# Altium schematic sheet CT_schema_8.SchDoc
size 382 x 278 mm
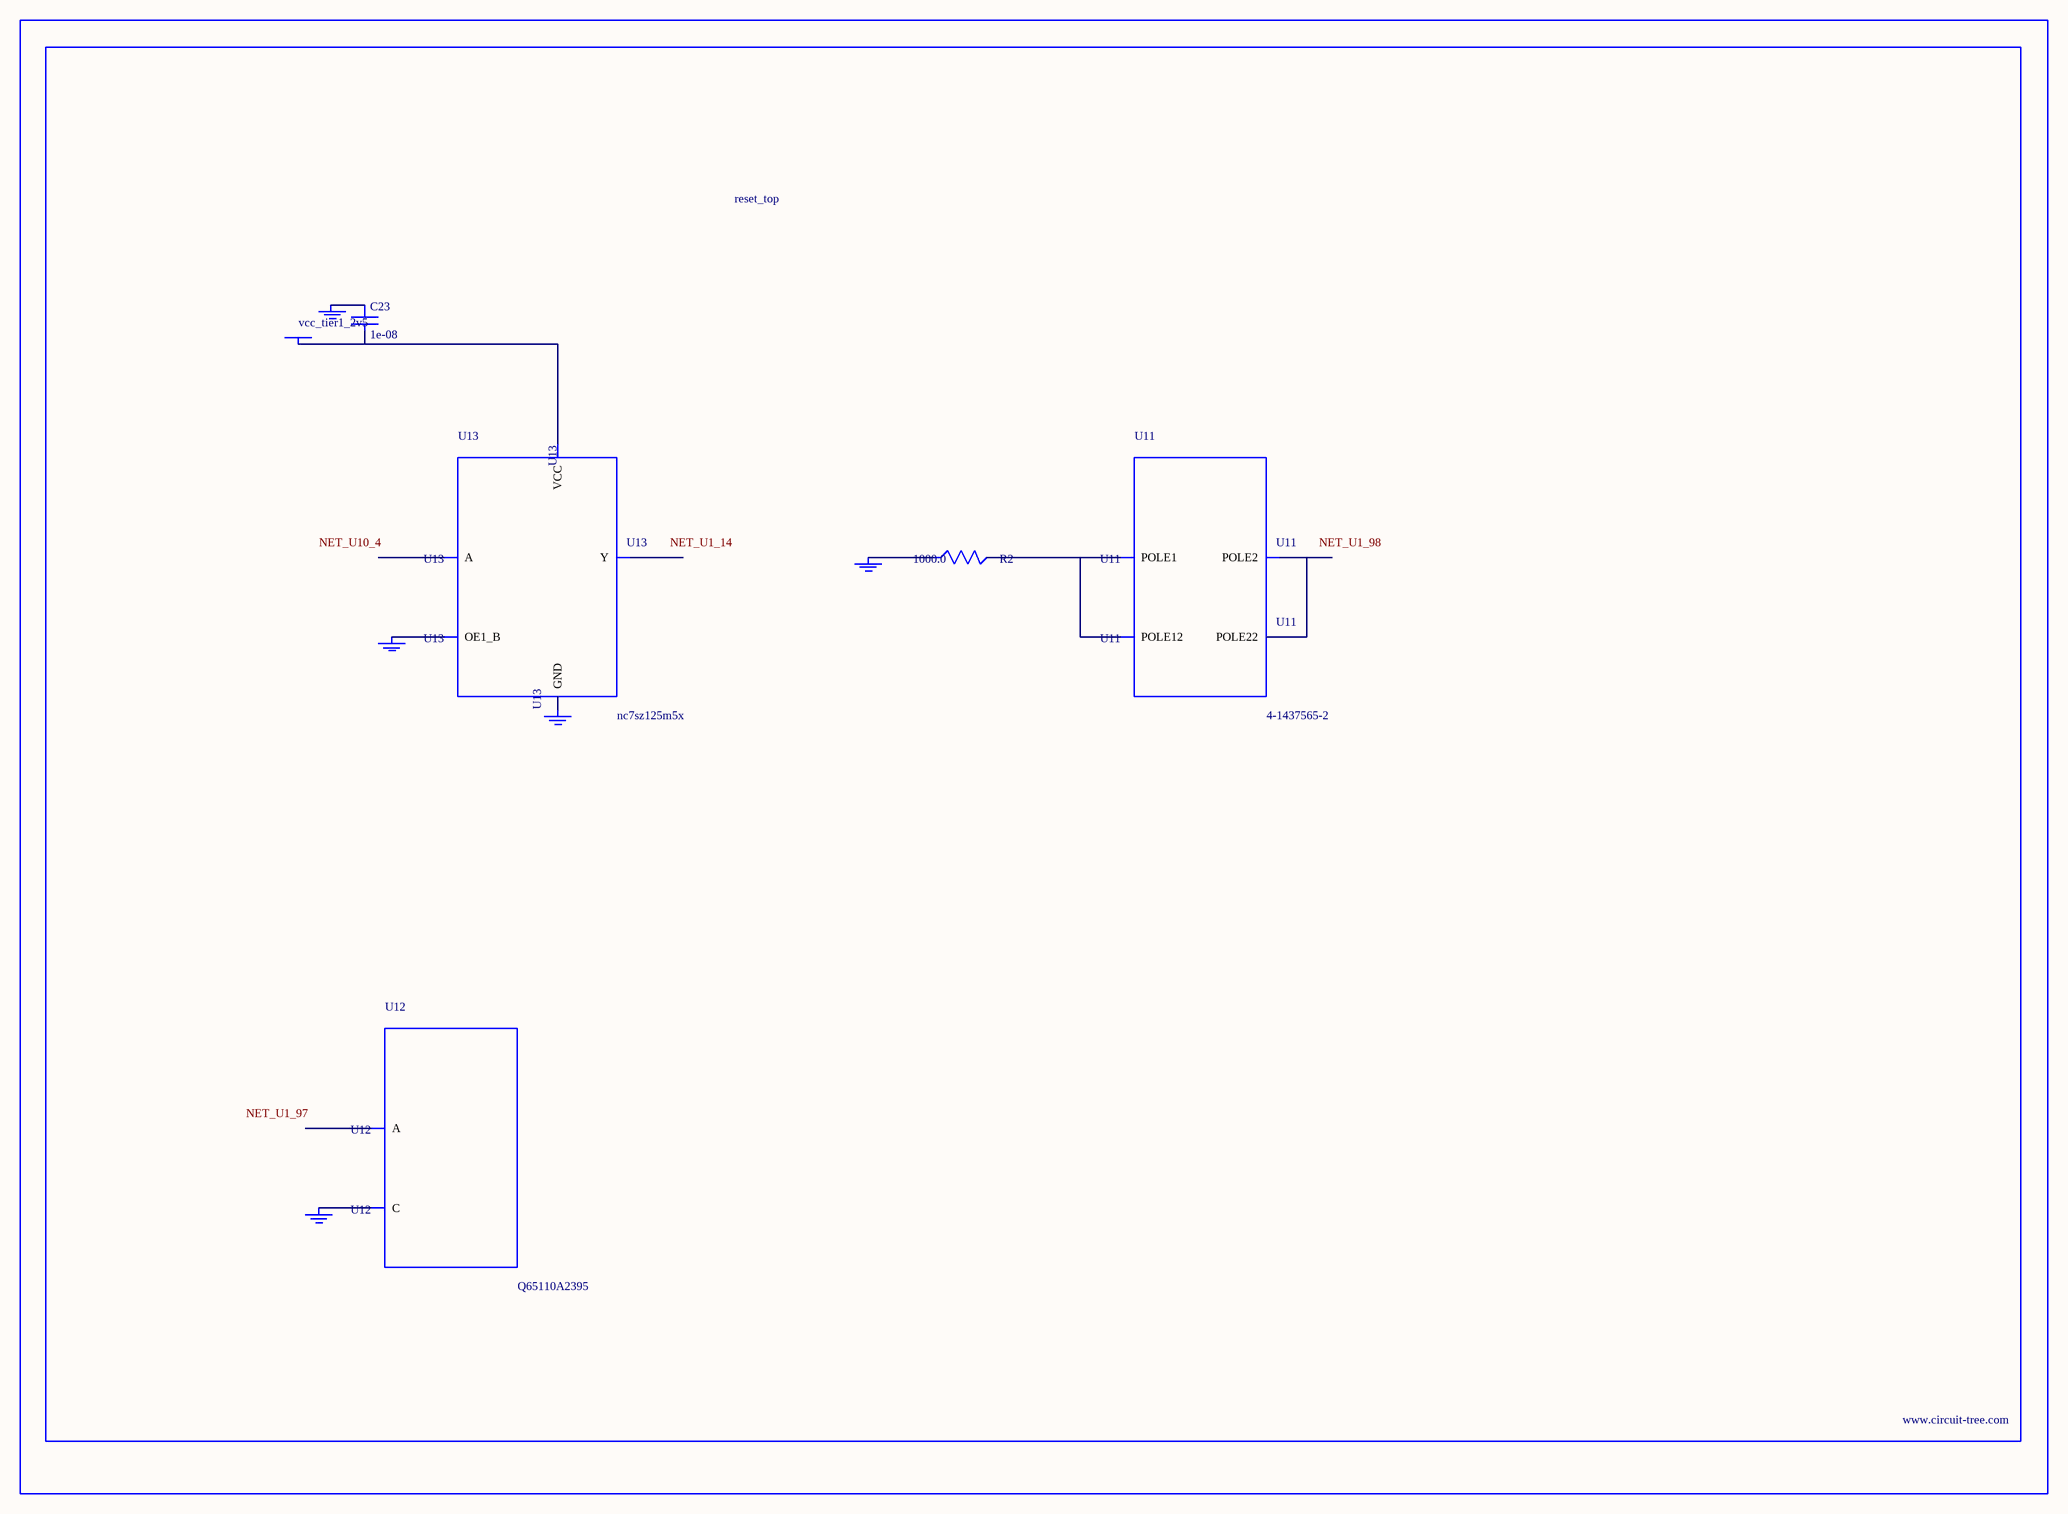
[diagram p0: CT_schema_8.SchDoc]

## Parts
BORDER7  (no value)
C23  1e-08  [C0402]
GND_INSTANCE_7_0  (no value)
GND_INSTANCE_7_1  (no value)
GND_INSTANCE_7_2  (no value)
GND_INSTANCE_7_3  (no value)
GND_INSTANCE_7_4  (no value)
POWER_INSTANCE_7_0  vcc_tier1_2v5
R2  1000.0  [R0603]
U11  4-1437565-2  [SW_4-1437565-2]
U12  Q65110A2395  [LGM67K-G1J2-24-Z]
U13  nc7sz125m5x  [NC7SZ125M5X]

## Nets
NetC23_1: C23.1 GND_INSTANCE_7_2.0(GND)
NetC23_2: C23.2 POWER_INSTANCE_7_0.0(PWR) U13.5(VCC)
NetGND_INSTANCE_7_0_0: GND_INSTANCE_7_0.0(GND) R2.1
NetGND_INSTANCE_7_1_0: GND_INSTANCE_7_1.0(GND) U12.C
NetGND_INSTANCE_7_3_0: GND_INSTANCE_7_3.0(GND) U13.1(OE1_B)
NetGND_INSTANCE_7_4_0: GND_INSTANCE_7_4.0(GND) U13.3(GND)
NetR2_2: R2.2 U11.1(POLE1) U11.2(POLE12)
NetU11_3: U11.3(POLE2) U11.4(POLE22)

Not connected (* = marked no-connect by the designer): U12 A; U13 2(A) 4(Y)

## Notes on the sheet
- Labels drawn without touching a wire or pin: NET_U1_14, NET_U1_97, NET_U1_98, NET_U10_4

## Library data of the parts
BORDER7 = BORDER_PAGE7
C23 = C0402C103K3RAC
GND_INSTANCE_7_0-GND_INSTANCE_7_4 = GND
POWER_INSTANCE_7_0 = PWR
R2 = RC0603JR-071KL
